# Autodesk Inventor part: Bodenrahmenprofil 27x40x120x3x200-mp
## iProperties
Created: 2010-02
Part Number: Bodenrahmenprofil 27x40x120x3x200-mp
Document SubType Name: Blech
Designer: JM
Density: 1 g/cm^3
Sheet Metal Rule: Standard
Mass: 1494.7 g
Surface Area: 10120.7 cm^2
Volume: 1494.7 cm^3
Author: JM
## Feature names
1. Extrusion1
2. Extrusion2
3. Extrusion3
